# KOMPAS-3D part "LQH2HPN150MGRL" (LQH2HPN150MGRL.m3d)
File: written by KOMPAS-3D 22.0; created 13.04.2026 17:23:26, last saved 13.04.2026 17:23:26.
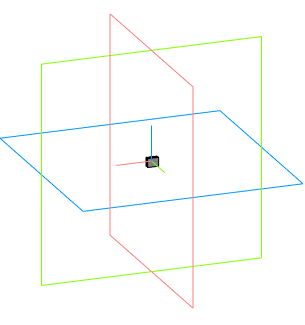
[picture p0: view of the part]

Document properties: Автор: Andrey; Полное имя файла: C:\Users\User1\Documents\LQH2HPN150MGRL.m3d

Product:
- Part/product: LQH2HPN150MGRL

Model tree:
1. Операция без истории:1
2. Операция без истории:2
3. Операция без истории:3
4. Операция без истории:4
5. Операция без истории:5
6. Операция без истории:6
7. Операция без истории:7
